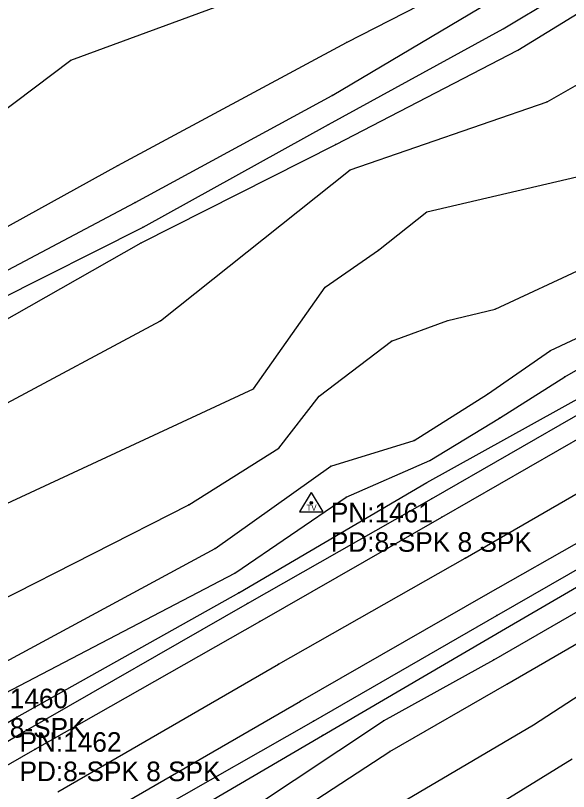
# Model space of a CAD drawing. Extents: x 1419505 to 1434054, y 1956910 to 1968644.
# Drawn here: x 1422254.5 to 1422395.6, y 1958500.2 to 1958698.2 of the extents above; entities that cross this region are included whole.
import ezdxf

# ---------------------------------------------------------------- set-up
doc = ezdxf.new("R2010")
doc.units = 0
for name, color, linetype in [('S_BREAKLINE', 7, 'Continuous'), ('S_DITCHLINE', 7, 'Continuous'), ('S_EDGE_PAVEMENT', 7, 'Continuous'), ('S_GRD_PT_SYM', 7, 'Continuous'), ('S_PAVEMENT_CROWN', 7, 'Continuous'), ('S_RDW_PT_SYM', 7, 'Continuous'), ('S_SECONDARY_CTL', 7, 'Continuous'), ('S_SECONDARY_CTL_ANNOT', 7, 'Continuous'), ('S_SHOULDER', 7, 'Continuous')]:
    doc.layers.add(name, color=color, linetype=linetype)

msp = doc.modelspace()

# ---------------------------------------------------------------- linework, layer by layer
at = {"layer": 'S_BREAKLINE'}
for p, q in [((1422382.7101, 1958689.3782), (1422441.0538, 1958725.3215)), ((1422268.6517, 1958686.875), (1422363.0758, 1958721.6443)), ((1422390.1545, 1958676.2194), (1422450.1924, 1958710.4926)), ((1422338.9442, 1958691.3223), (1422370.8093, 1958707.8414)), ((1422280.6525, 1958659.9953), (1422338.9442, 1958691.3223)), ((1422336.2331, 1958665.3416), (1422382.7101, 1958689.3782)), ((1422204.2785, 1958638.2459), (1422268.6517, 1958686.875)), ((1422339.9143, 1958658.8902), (1422390.1545, 1958676.2194)), ((1422286.6188, 1958640.224), (1422336.2331, 1958665.3416)), ((1422209.4879, 1958620.7028), (1422280.6525, 1958659.9953)), ((1422291.5122, 1958620.3447), (1422339.9143, 1958658.8902)), ((1422359.4856, 1958648.0975), (1422401.2202, 1958657.9362)), ((1422347.0948, 1958638.3749), (1422359.4856, 1958648.0975)), ((1422217.4194, 1958600.9395), (1422286.6188, 1958640.224)), ((1422376.8577, 1958623.2629), (1422412.872, 1958640.073)), ((1422333.5479, 1958628.8773), (1422347.0948, 1958638.3749)), ((1422315.2077, 1958602.9176), (1422333.5479, 1958628.8773)), ((1422391.0466, 1958612.7583), (1422418.8514, 1958625.8221)), ((1422364.8509, 1958620.3817), (1422376.8577, 1958623.2629)), ((1422222.6847, 1958583.4124), (1422291.5122, 1958620.3447)), ((1422350.408, 1958615.1384), (1422364.8509, 1958620.3817)), ((1422394.6328, 1958606.0288), (1422421.2215, 1958621.4938)), ((1422332.0058, 1958601.1095), (1422350.408, 1958615.1384)), ((1422374.9105, 1958601.5605), (1422391.0466, 1958612.7583)), ((1422359.4726, 1958579.0301), (1422410.3008, 1958607.2949)), ((1422377.9787, 1958595.4911), (1422394.6328, 1958606.0288)), ((1422222.9287, 1958560.0058), (1422315.2077, 1958602.9176)), ((1422321.7031, 1958587.8296), (1422332.0058, 1958601.1095)), ((1422356.2273, 1958589.7768), (1422374.9105, 1958601.5605)), ((1422360.2696, 1958584.6944), (1422377.9787, 1958595.4911)), ((1422334.951, 1958583.1803), (1422356.2273, 1958589.7768)), ((1422298.7356, 1958573.3577), (1422321.7031, 1958587.8296)), ((1422338.8612, 1958575.2758), (1422360.2696, 1958584.6944)), ((1422305.4621, 1958562.206), (1422334.951, 1958583.1803)), ((1422311.4885, 1958550.9003), (1422359.4726, 1958579.0301)), ((1422310.4864, 1958555.9016), (1422338.8612, 1958575.2758)), ((1422234.0895, 1958540.4656), (1422298.7356, 1958573.3577)), ((1422379.5428, 1958541.7597), (1422429.9161, 1958571.1386)), ((1422376.5187, 1958533.7862), (1422430.1541, 1958564.6961)), ((1422238.1857, 1958525.8566), (1422305.4621, 1958562.206)), ((1422379.8909, 1958527.5858), (1422433.6193, 1958558.8038)), ((1422241.3359, 1958519.7802), (1422310.4864, 1958555.9016)), ((1422254.8568, 1958519.1662), (1422311.4885, 1958550.9003)), ((1422386.7113, 1958517.1431), (1422439.6027, 1958551.7483)), ((1422332.8038, 1958514.4759), (1422379.5428, 1958541.7597)), ((1422348.3918, 1958518.1911), (1422376.5187, 1958533.7862)), ((1422350.0299, 1958510.3676), (1422379.8909, 1958527.5858)), ((1422222.3557, 1958500.178), (1422254.8568, 1958519.1662)), ((1422297.7716, 1958484.658), (1422348.3918, 1958518.1911)), ((1422346.9367, 1958493.7916), (1422386.7113, 1958517.1431)), ((1422274.197, 1958480.1797), (1422332.8038, 1958514.4759)), ((1422304.281, 1958480.5957), (1422350.0299, 1958510.3676)), ((1422351.098, 1958480.5897), (1422396.5669, 1958508.5065))]:
    msp.add_line(p, q, dxfattribs=at)
at = {"layer": 'S_DITCHLINE'}
for p, q in [((1422378.9548, 1958694.8296), (1422437.9216, 1958730.4209)), ((1422335.302, 1958677.8055), (1422375.4556, 1958701.666)), ((1422334.3919, 1958670.458), (1422378.9548, 1958694.8296)), ((1422285.0457, 1958650.5227), (1422335.302, 1958677.8055)), ((1422287.0649, 1958644.2543), (1422334.3919, 1958670.458)), ((1422212.179, 1958611.9682), (1422285.0457, 1958650.5227)), ((1422213.5161, 1958607.0929), (1422287.0649, 1958644.2543))]:
    msp.add_line(p, q, dxfattribs=at)
at = {"layer": 'S_EDGE_PAVEMENT'}
for p, q in [((1422363.2818, 1958570.2055), (1422414.9011, 1958599.8904)), ((1422374.5395, 1958550.3272), (1422425.6748, 1958579.5971)), ((1422316.8218, 1958543.5778), (1422363.2818, 1958570.2055)), ((1422327.2015, 1958523.2385), (1422374.5395, 1958550.3272)), ((1422259.5411, 1958510.9647), (1422316.8218, 1958543.5778)), ((1422269.5047, 1958489.9113), (1422327.2015, 1958523.2385)), ((1422226.608, 1958492.1505), (1422259.5411, 1958510.9647))]:
    msp.add_line(p, q, dxfattribs=at)
at = {"layer": 'S_GRD_PT_SYM'}
for points in [[(1422378.9548, 1958694.8296), (1422378.9548, 1958694.8796), (1422378.9548, 1958694.8296), (1422378.9048, 1958694.8296), (1422378.9548, 1958694.8296), (1422378.9548, 1958694.7796), (1422378.9548, 1958694.8296), (1422379.0048, 1958694.8296)], [(1422338.9442, 1958691.3223), (1422338.9442, 1958691.3723), (1422338.9442, 1958691.3223), (1422338.8942, 1958691.3223), (1422338.9442, 1958691.3223), (1422338.9442, 1958691.2723), (1422338.9442, 1958691.3223), (1422338.9942, 1958691.3223)], [(1422382.7101, 1958689.3782), (1422382.7101, 1958689.4282), (1422382.7101, 1958689.3782), (1422382.6601, 1958689.3782), (1422382.7101, 1958689.3782), (1422382.7101, 1958689.3282), (1422382.7101, 1958689.3782), (1422382.7601, 1958689.3782)], [(1422268.6517, 1958686.875), (1422268.6517, 1958686.925), (1422268.6517, 1958686.875), (1422268.6017, 1958686.875), (1422268.6517, 1958686.875), (1422268.6517, 1958686.825), (1422268.6517, 1958686.875), (1422268.7017, 1958686.875)], [(1422335.302, 1958677.8055), (1422335.302, 1958677.8555), (1422335.302, 1958677.8055), (1422335.252, 1958677.8055), (1422335.302, 1958677.8055), (1422335.302, 1958677.7555), (1422335.302, 1958677.8055), (1422335.352, 1958677.8055)], [(1422390.1545, 1958676.2194), (1422390.1545, 1958676.2694), (1422390.1545, 1958676.2194), (1422390.1045, 1958676.2194), (1422390.1545, 1958676.2194), (1422390.1545, 1958676.1694), (1422390.1545, 1958676.2194), (1422390.2045, 1958676.2194)], [(1422334.3919, 1958670.458), (1422334.3919, 1958670.508), (1422334.3919, 1958670.458), (1422334.3419, 1958670.458), (1422334.3919, 1958670.458), (1422334.3919, 1958670.408), (1422334.3919, 1958670.458), (1422334.4419, 1958670.458)], [(1422336.2331, 1958665.3416), (1422336.2331, 1958665.3916), (1422336.2331, 1958665.3416), (1422336.1831, 1958665.3416), (1422336.2331, 1958665.3416), (1422336.2331, 1958665.2916), (1422336.2331, 1958665.3416), (1422336.2831, 1958665.3416)], [(1422280.6525, 1958659.9953), (1422280.6525, 1958660.0453), (1422280.6525, 1958659.9953), (1422280.6025, 1958659.9953), (1422280.6525, 1958659.9953), (1422280.6525, 1958659.9453), (1422280.6525, 1958659.9953), (1422280.7025, 1958659.9953)], [(1422339.9143, 1958658.8902), (1422339.9143, 1958658.9402), (1422339.9143, 1958658.8902), (1422339.8643, 1958658.8902), (1422339.9143, 1958658.8902), (1422339.9143, 1958658.8402), (1422339.9143, 1958658.8902), (1422339.9643, 1958658.8902)], [(1422285.0457, 1958650.5227), (1422285.0457, 1958650.5727), (1422285.0457, 1958650.5227), (1422284.9957, 1958650.5227), (1422285.0457, 1958650.5227), (1422285.0457, 1958650.4727), (1422285.0457, 1958650.5227), (1422285.0957, 1958650.5227)], [(1422359.4856, 1958648.0975), (1422359.4856, 1958648.1475), (1422359.4856, 1958648.0975), (1422359.4356, 1958648.0975), (1422359.4856, 1958648.0975), (1422359.4856, 1958648.0475), (1422359.4856, 1958648.0975), (1422359.5356, 1958648.0975)], [(1422287.0649, 1958644.2543), (1422287.0649, 1958644.3043), (1422287.0649, 1958644.2543), (1422287.0149, 1958644.2543), (1422287.0649, 1958644.2543), (1422287.0649, 1958644.2043), (1422287.0649, 1958644.2543), (1422287.1149, 1958644.2543)], [(1422286.6188, 1958640.224), (1422286.6188, 1958640.274), (1422286.6188, 1958640.224), (1422286.5688, 1958640.224), (1422286.6188, 1958640.224), (1422286.6188, 1958640.174), (1422286.6188, 1958640.224), (1422286.6688, 1958640.224)], [(1422347.0948, 1958638.3749), (1422347.0948, 1958638.4249), (1422347.0948, 1958638.3749), (1422347.0448, 1958638.3749), (1422347.0948, 1958638.3749), (1422347.0948, 1958638.3249), (1422347.0948, 1958638.3749), (1422347.1448, 1958638.3749)], [(1422333.5479, 1958628.8773), (1422333.5479, 1958628.9273), (1422333.5479, 1958628.8773), (1422333.4979, 1958628.8773), (1422333.5479, 1958628.8773), (1422333.5479, 1958628.8273), (1422333.5479, 1958628.8773), (1422333.5979, 1958628.8773)], [(1422376.8577, 1958623.2629), (1422376.8577, 1958623.3129), (1422376.8577, 1958623.2629), (1422376.8077, 1958623.2629), (1422376.8577, 1958623.2629), (1422376.8577, 1958623.2129), (1422376.8577, 1958623.2629), (1422376.9077, 1958623.2629)], [(1422291.5122, 1958620.3447), (1422291.5122, 1958620.3947), (1422291.5122, 1958620.3447), (1422291.4622, 1958620.3447), (1422291.5122, 1958620.3447), (1422291.5122, 1958620.2947), (1422291.5122, 1958620.3447), (1422291.5622, 1958620.3447)], [(1422364.8509, 1958620.3817), (1422364.8509, 1958620.4317), (1422364.8509, 1958620.3817), (1422364.8009, 1958620.3817), (1422364.8509, 1958620.3817), (1422364.8509, 1958620.3317), (1422364.8509, 1958620.3817), (1422364.9009, 1958620.3817)], [(1422350.408, 1958615.1384), (1422350.408, 1958615.1884), (1422350.408, 1958615.1384), (1422350.358, 1958615.1384), (1422350.408, 1958615.1384), (1422350.408, 1958615.0884), (1422350.408, 1958615.1384), (1422350.458, 1958615.1384)], [(1422391.0466, 1958612.7583), (1422391.0466, 1958612.8083), (1422391.0466, 1958612.7583), (1422390.9966, 1958612.7583), (1422391.0466, 1958612.7583), (1422391.0466, 1958612.7083), (1422391.0466, 1958612.7583), (1422391.0966, 1958612.7583)], [(1422394.6328, 1958606.0288), (1422394.6328, 1958606.0788), (1422394.6328, 1958606.0288), (1422394.5828, 1958606.0288), (1422394.6328, 1958606.0288), (1422394.6328, 1958605.9788), (1422394.6328, 1958606.0288), (1422394.6828, 1958606.0288)], [(1422315.2077, 1958602.9176), (1422315.2077, 1958602.9676), (1422315.2077, 1958602.9176), (1422315.1577, 1958602.9176), (1422315.2077, 1958602.9176), (1422315.2077, 1958602.8676), (1422315.2077, 1958602.9176), (1422315.2577, 1958602.9176)], [(1422332.0058, 1958601.1095), (1422332.0058, 1958601.1595), (1422332.0058, 1958601.1095), (1422331.9558, 1958601.1095), (1422332.0058, 1958601.1095), (1422332.0058, 1958601.0595), (1422332.0058, 1958601.1095), (1422332.0558, 1958601.1095)], [(1422374.9105, 1958601.5605), (1422374.9105, 1958601.6105), (1422374.9105, 1958601.5605), (1422374.8605, 1958601.5605), (1422374.9105, 1958601.5605), (1422374.9105, 1958601.5105), (1422374.9105, 1958601.5605), (1422374.9605, 1958601.5605)], [(1422377.9787, 1958595.4911), (1422377.9787, 1958595.5411), (1422377.9787, 1958595.4911), (1422377.9287, 1958595.4911), (1422377.9787, 1958595.4911), (1422377.9787, 1958595.4411), (1422377.9787, 1958595.4911), (1422378.0287, 1958595.4911)], [(1422356.2273, 1958589.7768), (1422356.2273, 1958589.8268), (1422356.2273, 1958589.7768), (1422356.1773, 1958589.7768), (1422356.2273, 1958589.7768), (1422356.2273, 1958589.7268), (1422356.2273, 1958589.7768), (1422356.2773, 1958589.7768)], [(1422321.7031, 1958587.8296), (1422321.7031, 1958587.8796), (1422321.7031, 1958587.8296), (1422321.6531, 1958587.8296), (1422321.7031, 1958587.8296), (1422321.7031, 1958587.7796), (1422321.7031, 1958587.8296), (1422321.7531, 1958587.8296)], [(1422360.2696, 1958584.6944), (1422360.2696, 1958584.7444), (1422360.2696, 1958584.6944), (1422360.2196, 1958584.6944), (1422360.2696, 1958584.6944), (1422360.2696, 1958584.6444), (1422360.2696, 1958584.6944), (1422360.3196, 1958584.6944)], [(1422334.951, 1958583.1803), (1422334.951, 1958583.2303), (1422334.951, 1958583.1803), (1422334.901, 1958583.1803), (1422334.951, 1958583.1803), (1422334.951, 1958583.1303), (1422334.951, 1958583.1803), (1422335.001, 1958583.1803)], [(1422359.4726, 1958579.0301), (1422359.4726, 1958579.0801), (1422359.4726, 1958579.0301), (1422359.4226, 1958579.0301), (1422359.4726, 1958579.0301), (1422359.4726, 1958578.9801), (1422359.4726, 1958579.0301), (1422359.5226, 1958579.0301)], [(1422338.8612, 1958575.2758), (1422338.8612, 1958575.3258), (1422338.8612, 1958575.2758), (1422338.8112, 1958575.2758), (1422338.8612, 1958575.2758), (1422338.8612, 1958575.2258), (1422338.8612, 1958575.2758), (1422338.9112, 1958575.2758)], [(1422298.7356, 1958573.3577), (1422298.7356, 1958573.4077), (1422298.7356, 1958573.3577), (1422298.6856, 1958573.3577), (1422298.7356, 1958573.3577), (1422298.7356, 1958573.3077), (1422298.7356, 1958573.3577), (1422298.7856, 1958573.3577)], [(1422305.4621, 1958562.206), (1422305.4621, 1958562.256), (1422305.4621, 1958562.206), (1422305.4121, 1958562.206), (1422305.4621, 1958562.206), (1422305.4621, 1958562.156), (1422305.4621, 1958562.206), (1422305.5121, 1958562.206)], [(1422310.4864, 1958555.9016), (1422310.4864, 1958555.9516), (1422310.4864, 1958555.9016), (1422310.4364, 1958555.9016), (1422310.4864, 1958555.9016), (1422310.4864, 1958555.8516), (1422310.4864, 1958555.9016), (1422310.5364, 1958555.9016)], [(1422311.4885, 1958550.9003), (1422311.4885, 1958550.9503), (1422311.4885, 1958550.9003), (1422311.4385, 1958550.9003), (1422311.4885, 1958550.9003), (1422311.4885, 1958550.8503), (1422311.4885, 1958550.9003), (1422311.5385, 1958550.9003)], [(1422379.5428, 1958541.7597), (1422379.5428, 1958541.8097), (1422379.5428, 1958541.7597), (1422379.4928, 1958541.7597), (1422379.5428, 1958541.7597), (1422379.5428, 1958541.7097), (1422379.5428, 1958541.7597), (1422379.5928, 1958541.7597)], [(1422376.5187, 1958533.7862), (1422376.5187, 1958533.8362), (1422376.5187, 1958533.7862), (1422376.4687, 1958533.7862), (1422376.5187, 1958533.7862), (1422376.5187, 1958533.7362), (1422376.5187, 1958533.7862), (1422376.5687, 1958533.7862)], [(1422379.8909, 1958527.5858), (1422379.8909, 1958527.6358), (1422379.8909, 1958527.5858), (1422379.8409, 1958527.5858), (1422379.8909, 1958527.5858), (1422379.8909, 1958527.5358), (1422379.8909, 1958527.5858), (1422379.9409, 1958527.5858)], [(1422254.8568, 1958519.1662), (1422254.8568, 1958519.2162), (1422254.8568, 1958519.1662), (1422254.8068, 1958519.1662), (1422254.8568, 1958519.1662), (1422254.8568, 1958519.1162), (1422254.8568, 1958519.1662), (1422254.9068, 1958519.1662)], [(1422348.3918, 1958518.1911), (1422348.3918, 1958518.2411), (1422348.3918, 1958518.1911), (1422348.3418, 1958518.1911), (1422348.3918, 1958518.1911), (1422348.3918, 1958518.1411), (1422348.3918, 1958518.1911), (1422348.4418, 1958518.1911)], [(1422386.7113, 1958517.1431), (1422386.7113, 1958517.1931), (1422386.7113, 1958517.1431), (1422386.6613, 1958517.1431), (1422386.7113, 1958517.1431), (1422386.7113, 1958517.0931), (1422386.7113, 1958517.1431), (1422386.7613, 1958517.1431)], [(1422332.8038, 1958514.4759), (1422332.8038, 1958514.5259), (1422332.8038, 1958514.4759), (1422332.7538, 1958514.4759), (1422332.8038, 1958514.4759), (1422332.8038, 1958514.4259), (1422332.8038, 1958514.4759), (1422332.8538, 1958514.4759)], [(1422350.0299, 1958510.3676), (1422350.0299, 1958510.4176), (1422350.0299, 1958510.3676), (1422349.9799, 1958510.3676), (1422350.0299, 1958510.3676), (1422350.0299, 1958510.3176), (1422350.0299, 1958510.3676), (1422350.0799, 1958510.3676)]]:
    msp.add_lwpolyline(points, dxfattribs=at)
at = {"layer": 'S_PAVEMENT_CROWN'}
for p, q in [((1422369.2062, 1958559.7138), (1422419.9995, 1958589.1487)), ((1422321.5881, 1958532.6841), (1422369.2062, 1958559.7138)), ((1422265.2935, 1958500.111), (1422321.5881, 1958532.6841))]:
    msp.add_line(p, q, dxfattribs=at)
at = {"layer": 'S_RDW_PT_SYM'}
for points in [[(1422360.6196, 1958574.8538), (1422360.6196, 1958574.9038), (1422360.6196, 1958574.8538), (1422360.5696, 1958574.8538), (1422360.6196, 1958574.8538), (1422360.6196, 1958574.8038), (1422360.6196, 1958574.8538), (1422360.6696, 1958574.8538)], [(1422363.2818, 1958570.2055), (1422363.2818, 1958570.2555), (1422363.2818, 1958570.2055), (1422363.2318, 1958570.2055), (1422363.2818, 1958570.2055), (1422363.2818, 1958570.1555), (1422363.2818, 1958570.2055), (1422363.3318, 1958570.2055)], [(1422369.2062, 1958559.7138), (1422369.2062, 1958559.7638), (1422369.2062, 1958559.7138), (1422369.1562, 1958559.7138), (1422369.2062, 1958559.7138), (1422369.2062, 1958559.6638), (1422369.2062, 1958559.7138), (1422369.2562, 1958559.7138)], [(1422374.5395, 1958550.3272), (1422374.5395, 1958550.3772), (1422374.5395, 1958550.3272), (1422374.4895, 1958550.3272), (1422374.5395, 1958550.3272), (1422374.5395, 1958550.2772), (1422374.5395, 1958550.3272), (1422374.5895, 1958550.3272)], [(1422313.6686, 1958548.1631), (1422313.6686, 1958548.2131), (1422313.6686, 1958548.1631), (1422313.6186, 1958548.1631), (1422313.6686, 1958548.1631), (1422313.6686, 1958548.1131), (1422313.6686, 1958548.1631), (1422313.7186, 1958548.1631)], [(1422377.3217, 1958545.1219), (1422377.3217, 1958545.1719), (1422377.3217, 1958545.1219), (1422377.2717, 1958545.1219), (1422377.3217, 1958545.1219), (1422377.3217, 1958545.0719), (1422377.3217, 1958545.1219), (1422377.3717, 1958545.1219)], [(1422316.8218, 1958543.5778), (1422316.8218, 1958543.6278), (1422316.8218, 1958543.5778), (1422316.7718, 1958543.5778), (1422316.8218, 1958543.5778), (1422316.8218, 1958543.5278), (1422316.8218, 1958543.5778), (1422316.8718, 1958543.5778)], [(1422321.5881, 1958532.6841), (1422321.5881, 1958532.7341), (1422321.5881, 1958532.6841), (1422321.5381, 1958532.6841), (1422321.5881, 1958532.6841), (1422321.5881, 1958532.6341), (1422321.5881, 1958532.6841), (1422321.6381, 1958532.6841)], [(1422327.2015, 1958523.2385), (1422327.2015, 1958523.2885), (1422327.2015, 1958523.2385), (1422327.1515, 1958523.2385), (1422327.2015, 1958523.2385), (1422327.2015, 1958523.1885), (1422327.2015, 1958523.2385), (1422327.2515, 1958523.2385)], [(1422330.5527, 1958518.1131), (1422330.5527, 1958518.1631), (1422330.5527, 1958518.1131), (1422330.5027, 1958518.1131), (1422330.5527, 1958518.1131), (1422330.5527, 1958518.0631), (1422330.5527, 1958518.1131), (1422330.6027, 1958518.1131)], [(1422256.4729, 1958515.288), (1422256.4729, 1958515.338), (1422256.4729, 1958515.288), (1422256.4229, 1958515.288), (1422256.4729, 1958515.288), (1422256.4729, 1958515.238), (1422256.4729, 1958515.288), (1422256.5229, 1958515.288)], [(1422259.5411, 1958510.9647), (1422259.5411, 1958511.0147), (1422259.5411, 1958510.9647), (1422259.4911, 1958510.9647), (1422259.5411, 1958510.9647), (1422259.5411, 1958510.9147), (1422259.5411, 1958510.9647), (1422259.5911, 1958510.9647)]]:
    msp.add_lwpolyline(points, dxfattribs=at)
at = {"layer": 'S_SECONDARY_CTL'}
for p, q in [((1422329.9726, 1958576.4668), (1422326.9626, 1958571.5129)), ((1422329.9726, 1958576.4668), (1422332.9199, 1958571.5129)), ((1422326.9626, 1958571.5129), (1422332.9199, 1958571.5129))]:
    msp.add_line(p, q, dxfattribs=at)
for radius in [0.3111, 0.1827, 0.1033]:
    msp.add_circle((1422329.9726, 1958573.8567), radius, dxfattribs=at)
at = {"layer": 'S_SHOULDER'}
for p, q in [((1422360.6196, 1958574.8538), (1422412.647, 1958604.8277)), ((1422313.6686, 1958548.1631), (1422360.6196, 1958574.8538)), ((1422377.3217, 1958545.1219), (1422428.376, 1958574.4508)), ((1422256.4729, 1958515.288), (1422313.6686, 1958548.1631)), ((1422330.5527, 1958518.1131), (1422377.3217, 1958545.1219)), ((1422272.5179, 1958485.08), (1422330.5527, 1958518.1131)), ((1422224.1628, 1958496.6308), (1422256.4729, 1958515.288))]:
    msp.add_line(p, q, dxfattribs=at)

# ---------------------------------------------------------------- texts
at = {"layer": 'S_SECONDARY_CTL'}
msp.add_text('TV', height=1.5, rotation=360, dxfattribs=at).set_placement((1422328.7679, 1958571.8454))
at = {"layer": 'S_SECONDARY_CTL_ANNOT'}
for s, p in [('PN:1461', (1422334.9726, 1958568.8567)), ('PD:8-SPK 8 SPK', (1422334.9726, 1958561.3567)), ('PN:1460', (1422241.9196, 1958521.4137)), ('PD:8-SPK', (1422241.9196, 1958513.9137)), ('PN:1462', (1422255.5405, 1958510.306)), ('PD:8-SPK 8 SPK', (1422255.5405, 1958502.806))]:
    msp.add_text(s, height=5, dxfattribs=at).set_placement(p)

doc.saveas('drawing.dxf')
